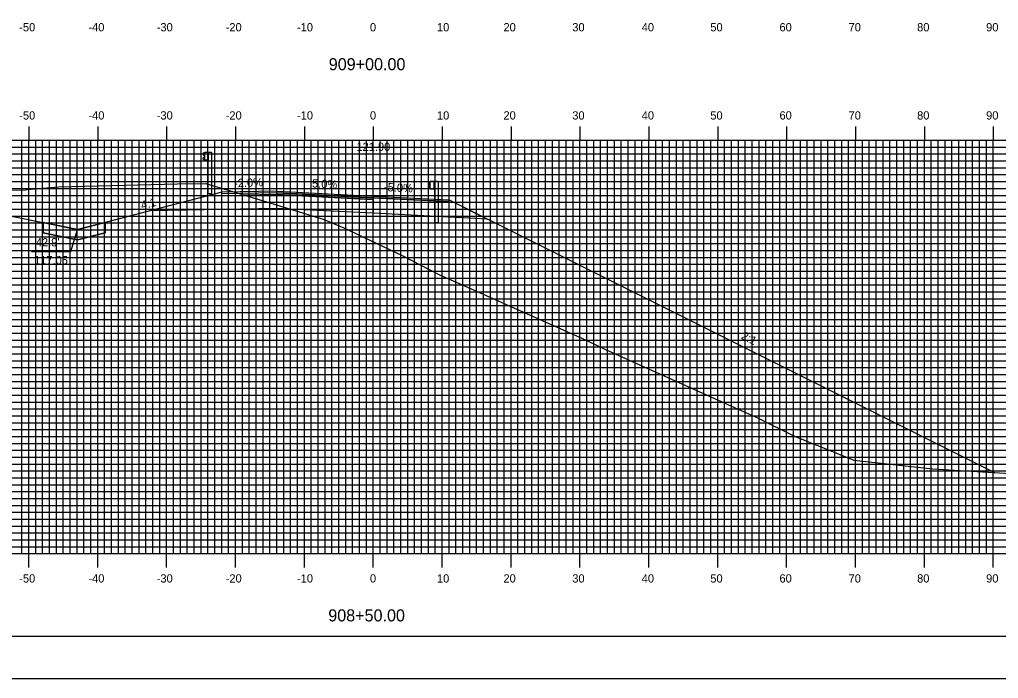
# Model space of a CAD drawing. Extents: x 858684 to 859027, y 364765 to 364985.
# Drawn here: x 858798.5 to 858940.6, y 364765.2 to 364860.8 of the extents above; entities that cross this region are included whole.
import ezdxf

# ---------------------------------------------------------------- set-up
doc = ezdxf.new("R2010")
doc.units = 0
for name, color, linetype in [('ANNOTATION', 7, 'Continuous'), ('BORDER', 7, 'Continuous'), ('D_Guardrail_Beam_Rt', 7, 'Continuous'), ('D_Roadway_Centerline', 7, 'Continuous'), ('D_Roadway_Centerline_Text', 7, 'Continuous'), ('D_Roadway_Edge_Shoulder', 7, 'Continuous'), ('D_Roadway_Edge_TW', 7, 'Continuous'), ('D_Roadway_FinishedGrade', 7, 'Continuous'), ('D_Roadway_Pavement', 7, 'Continuous'), ('D_Roadway_SlopeLines', 7, 'Continuous'), ('D_Roadway_SubGrade', 7, 'Continuous'), ('H_V ANNOTATION', 7, 'Continuous'), ('M_Guardrail', 7, 'Continuous'), ('M_Roadway_Centerline', 7, 'Continuous'), ('MAJOR', 7, 'Continuous'), ('MINOR', 7, 'Continuous'), ('PLOT BOUNDARY', 7, 'Continuous'), ('S_Roadway_Centerline', 7, 'Continuous')]:
    doc.layers.add(name, color=color, linetype=linetype)

msp = doc.modelspace()

# ---------------------------------------------------------------- linework, layer by layer
at = {"layer": 'ANNOTATION'}
msp.add_lwpolyline([(858800.26, 364827.16), (858805.95, 364827.16), (858806.92, 364830.35)], dxfattribs=at)
at = {"layer": 'BORDER'}
msp.add_lwpolyline([(858700.25, 364771.3), (859020.25, 364771.3), (859020.25, 364981.3), (858700.25, 364981.3)], close=True, dxfattribs=at)
at = {"layer": 'D_Guardrail_Beam_Rt'}
for p, q in [((858858.03, 364837.27), (858857.88, 364837.17)), ((858857.88, 364837.03), (858858.08, 364836.89)), ((858858.12, 364837.3), (858858.04, 364837.28)), ((858858.11, 364836.83), (858858.11, 364836.76)), ((858858.12, 364837.38), (858858.81, 364837.38)), ((858858.12, 364836.21), (858858.12, 364837.38)), ((858858.64, 364837.38), (858858.64, 364836.21)), ((858858.74, 364837.38), (858858.74, 364836.21)), ((858858.81, 364837.38), (858859.28, 364837.38)), ((858858.81, 364837.38), (858858.81, 364836.21)), ((858859.28, 364837.38), (858859.28, 364831.38)), ((858858.08, 364836.7), (858857.88, 364836.56)), ((858857.88, 364836.42), (858858.03, 364836.32)), ((858858.04, 364836.31), (858858.12, 364836.3)), ((858858.81, 364836.21), (858858.12, 364836.21)), ((858858.78, 364831.38), (858858.78, 364836.21)), ((858858.78, 364831.38), (858859.28, 364831.38))]:
    msp.add_line(p, q, dxfattribs=at)
for centre, major_axis, start_param, end_param in [((858857.94, 364837.1), (-0.0877, 0), 5.323254, 7.243116), ((858858.05, 364837.24), (-0.0417, 0), 4.907132, 5.323254), ((858858.03, 364836.83), (0.0789, 0), 0, 0.959931), ((858857.94, 364836.49), (-0.0877, 0), 5.323254, 7.243116), ((858858.05, 364836.35), (-0.0417, 0), 0.959931, 1.376053), ((858858.03, 364836.76), (0.0789, 0), 5.323254, 6.283185)]:
    msp.add_ellipse(centre, major_axis=major_axis, ratio=0.995501, start_param=start_param, end_param=end_param, dxfattribs=at)
at = {"layer": 'D_Roadway_Centerline'}
msp.add_lwpolyline([(858780.52, 364835.65), (858806.92, 364830.35)], dxfattribs=at)
at = {"layer": 'D_Roadway_Edge_Shoulder'}
for p, q in [((858835.85, 364835.91), (858827.85, 364835.75)), ((858827.85, 364835.5), (858827.85, 364835.75)), ((858835.85, 364835.66), (858827.85, 364835.5)), ((858830.85, 364835.46), (858830.85, 364835.56))]:
    msp.add_line(p, q, dxfattribs=at)
msp.add_lwpolyline([(858835.85, 364835.41), (858830.85, 364835.31), (858830.85, 364835.46)], dxfattribs=at)
msp.add_lwpolyline([(858849.85, 364835.2), (858857.85, 364834.8), (858857.85, 364834.8), (858860.85, 364834.64), (858860.85, 364834.39), (858849.85, 364834.95)], close=True, dxfattribs=at)
at = {"layer": 'D_Roadway_Edge_TW'}
msp.add_lwpolyline([(858835.85, 364835.91), (858849.85, 364835.2), (858849.85, 364834.95), (858835.85, 364835.66)], close=True, dxfattribs=at)
at = {"layer": 'D_Roadway_FinishedGrade'}
msp.add_line((858810.92, 364831.35), (858806.92, 364830.35), dxfattribs=at)
msp.add_lwpolyline([(858810.92, 364831.35), (858810.92, 364829.85), (858806.92, 364828.85), (858801.94, 364829.85), (858801.94, 364831.35), (858806.92, 364830.35)], close=True, dxfattribs=at)
msp.add_lwpolyline([(858806.92, 364830.35), (858801.94, 364831.35), (858801.94, 364829.85), (858806.92, 364828.85), (858810.92, 364829.85), (858810.92, 364831.35)], dxfattribs=at)
at = {"layer": 'D_Roadway_Pavement'}
msp.add_lwpolyline([(858835.85, 364835.66), (858849.85, 364834.95), (858849.85, 364834.7), (858835.85, 364835.41)], close=True, dxfattribs=at)
msp.add_lwpolyline([(858849.85, 364834.95), (858849.85, 364834.7)], dxfattribs=at)
msp.add_lwpolyline([(858849.85, 364834.95), (858849.85, 364834.7)], dxfattribs=at)
msp.add_lwpolyline([(858849.85, 364834.95), (858849.85, 364834.7)], dxfattribs=at)
at = {"layer": 'D_Roadway_SlopeLines'}
for p, q in [((858827.85, 364835.75), (858810.92, 364831.35)), ((858835.85, 364833.41), (858817.41, 364833.04))]:
    msp.add_line(p, q, dxfattribs=at)
msp.add_lwpolyline([(858860.85, 364834.64), (858940.02, 364795.06)], dxfattribs=at)
at = {"layer": 'D_Roadway_SubGrade'}
for points in [[(858835.85, 364835.41), (858849.85, 364834.7), (858849.85, 364832.7), (858835.85, 364833.41)], [(858849.85, 364834.7), (858849.85, 364834.95), (858860.85, 364834.39), (858860.85, 364834.64), (858866.41, 364831.86), (858849.85, 364832.7)]]:
    msp.add_lwpolyline(points, close=True, dxfattribs=at)
at = {"layer": 'M_Guardrail'}
for p, q in [((858825.28, 364841.45), (858825.14, 364841.35)), ((858825.14, 364841.21), (858825.33, 364841.07)), ((858825.38, 364841.47), (858825.3, 364841.46)), ((858825.38, 364841.55), (858825.87, 364841.55)), ((858825.38, 364840.38), (858825.38, 364841.55)), ((858825.87, 364841.55), (858826.36, 364841.55)), ((858825.87, 364841.55), (858825.87, 364840.38)), ((858826.36, 364841.55), (858826.36, 364835.55)), ((858825.33, 364840.85), (858825.14, 364840.72)), ((858825.14, 364840.57), (858825.28, 364840.47)), ((858825.3, 364840.47), (858825.38, 364840.45)), ((858825.37, 364841.01), (858825.37, 364840.92)), ((858825.87, 364840.38), (858825.38, 364840.38)), ((858825.87, 364835.55), (858825.87, 364840.38)), ((858825.87, 364835.55), (858826.36, 364835.55))]:
    msp.add_line(p, q, dxfattribs=at)
for centre, major_axis, start_param, end_param in [((858825.19, 364841.28), (-0.0877, 0), 5.323254, 7.243116), ((858825.3, 364841.42), (-0.0417, 0), 4.886922, 5.323254), ((858825.19, 364840.65), (-0.0877, 0), 5.323254, 7.243116), ((858825.3, 364840.51), (-0.0417, 0), 0.959931, 1.396263), ((858825.29, 364841.01), (0.0789, 0), 0, 0.959931), ((858825.29, 364840.92), (0.0789, 0), 5.323254, 6.283185)]:
    msp.add_ellipse(centre, major_axis=major_axis, ratio=0.995501, start_param=start_param, end_param=end_param, dxfattribs=at)
at = {"layer": 'MAJOR'}
for p, q in [((858799.85, 364845.31), (858799.85, 364843.3)), ((858809.85, 364845.31), (858809.85, 364843.3)), ((858819.85, 364845.31), (858819.85, 364843.3)), ((858829.85, 364845.31), (858829.85, 364843.3)), ((858839.85, 364845.31), (858839.85, 364843.3)), ((858849.85, 364845.31), (858849.85, 364843.3)), ((858859.85, 364845.31), (858859.85, 364843.3)), ((858869.85, 364845.31), (858869.85, 364843.3)), ((858879.85, 364845.31), (858879.85, 364843.3)), ((858889.85, 364845.31), (858889.85, 364843.3)), ((858899.85, 364845.31), (858899.85, 364843.3)), ((858909.85, 364845.31), (858909.85, 364843.3)), ((858919.85, 364845.31), (858919.85, 364843.3)), ((858929.85, 364845.31), (858929.85, 364843.3)), ((858939.85, 364845.31), (858939.85, 364843.3)), ((858709.85, 364843.3), (858989.85, 364843.3)), ((858709.85, 364843.3), (858989.85, 364843.3)), ((858799.85, 364783.3), (858799.85, 364843.3)), ((858809.85, 364783.3), (858809.85, 364843.3)), ((858819.85, 364783.3), (858819.85, 364843.3)), ((858829.85, 364783.3), (858829.85, 364843.3)), ((858839.85, 364783.3), (858839.85, 364843.3)), ((858849.85, 364783.3), (858849.85, 364843.3)), ((858859.85, 364783.3), (858859.85, 364843.3)), ((858869.85, 364783.3), (858869.85, 364843.3)), ((858879.85, 364783.3), (858879.85, 364843.3)), ((858889.85, 364783.3), (858889.85, 364843.3)), ((858899.85, 364783.3), (858899.85, 364843.3)), ((858909.85, 364783.3), (858909.85, 364843.3)), ((858919.85, 364783.3), (858919.85, 364843.3)), ((858929.85, 364783.3), (858929.85, 364843.3)), ((858939.85, 364783.3), (858939.85, 364843.3)), ((858709.85, 364838.3), (858989.85, 364838.3)), ((858709.85, 364833.3), (858989.85, 364833.3)), ((858709.85, 364828.3), (858989.85, 364828.3)), ((858709.85, 364823.3), (858989.85, 364823.3)), ((858709.85, 364818.3), (858989.85, 364818.3)), ((858709.85, 364813.3), (858989.85, 364813.3)), ((858709.85, 364808.3), (858989.85, 364808.3)), ((858709.85, 364803.3), (858989.85, 364803.3)), ((858709.85, 364798.3), (858989.85, 364798.3)), ((858709.85, 364793.3), (858989.85, 364793.3)), ((858709.85, 364788.3), (858989.85, 364788.3)), ((858709.85, 364783.3), (858989.85, 364783.3)), ((858709.85, 364783.3), (858989.85, 364783.3)), ((858799.85, 364781.3), (858799.85, 364783.3)), ((858809.85, 364781.3), (858809.85, 364783.3)), ((858819.85, 364781.3), (858819.85, 364783.3)), ((858829.85, 364781.3), (858829.85, 364783.3)), ((858839.85, 364781.3), (858839.85, 364783.3)), ((858849.85, 364781.3), (858849.85, 364783.3)), ((858859.85, 364781.3), (858859.85, 364783.3)), ((858869.85, 364781.3), (858869.85, 364783.3)), ((858879.85, 364781.3), (858879.85, 364783.3)), ((858889.85, 364781.3), (858889.85, 364783.3)), ((858899.85, 364781.3), (858899.85, 364783.3)), ((858909.85, 364781.3), (858909.85, 364783.3)), ((858919.85, 364781.3), (858919.85, 364783.3)), ((858929.85, 364781.3), (858929.85, 364783.3)), ((858939.85, 364781.3), (858939.85, 364783.3))]:
    msp.add_line(p, q, dxfattribs=at)
at = {"layer": 'MINOR'}
for p, q in [((858798.85, 364783.3), (858798.85, 364843.3)), ((858800.85, 364783.3), (858800.85, 364843.3)), ((858801.85, 364783.3), (858801.85, 364843.3)), ((858802.85, 364783.3), (858802.85, 364843.3)), ((858803.85, 364783.3), (858803.85, 364843.3)), ((858804.85, 364783.3), (858804.85, 364843.3)), ((858805.85, 364783.3), (858805.85, 364843.3)), ((858806.85, 364783.3), (858806.85, 364843.3)), ((858807.85, 364783.3), (858807.85, 364843.3)), ((858808.85, 364783.3), (858808.85, 364843.3)), ((858810.85, 364783.3), (858810.85, 364843.3)), ((858811.85, 364783.3), (858811.85, 364843.3)), ((858812.85, 364783.3), (858812.85, 364843.3)), ((858813.85, 364783.3), (858813.85, 364843.3)), ((858814.85, 364783.3), (858814.85, 364843.3)), ((858815.85, 364783.3), (858815.85, 364843.3)), ((858816.85, 364783.3), (858816.85, 364843.3)), ((858817.85, 364783.3), (858817.85, 364843.3)), ((858818.85, 364783.3), (858818.85, 364843.3)), ((858820.85, 364783.3), (858820.85, 364843.3)), ((858821.85, 364783.3), (858821.85, 364843.3)), ((858822.85, 364783.3), (858822.85, 364843.3)), ((858823.85, 364783.3), (858823.85, 364843.3)), ((858824.85, 364783.3), (858824.85, 364843.3)), ((858825.85, 364783.3), (858825.85, 364843.3)), ((858826.85, 364783.3), (858826.85, 364843.3)), ((858827.85, 364783.3), (858827.85, 364843.3)), ((858828.85, 364783.3), (858828.85, 364843.3)), ((858830.85, 364783.3), (858830.85, 364843.3)), ((858831.85, 364783.3), (858831.85, 364843.3)), ((858832.85, 364783.3), (858832.85, 364843.3)), ((858833.85, 364783.3), (858833.85, 364843.3)), ((858834.85, 364783.3), (858834.85, 364843.3)), ((858835.85, 364783.3), (858835.85, 364843.3)), ((858836.85, 364783.3), (858836.85, 364843.3)), ((858837.85, 364783.3), (858837.85, 364843.3)), ((858838.85, 364783.3), (858838.85, 364843.3)), ((858840.85, 364783.3), (858840.85, 364843.3)), ((858841.85, 364783.3), (858841.85, 364843.3)), ((858842.85, 364783.3), (858842.85, 364843.3)), ((858843.85, 364783.3), (858843.85, 364843.3)), ((858844.85, 364783.3), (858844.85, 364843.3)), ((858845.85, 364783.3), (858845.85, 364843.3)), ((858846.85, 364783.3), (858846.85, 364843.3)), ((858847.85, 364783.3), (858847.85, 364843.3)), ((858848.85, 364783.3), (858848.85, 364843.3)), ((858850.85, 364783.3), (858850.85, 364843.3)), ((858851.85, 364783.3), (858851.85, 364843.3)), ((858852.85, 364783.3), (858852.85, 364843.3)), ((858853.85, 364783.3), (858853.85, 364843.3)), ((858854.85, 364783.3), (858854.85, 364843.3)), ((858855.85, 364783.3), (858855.85, 364843.3)), ((858856.85, 364783.3), (858856.85, 364843.3)), ((858857.85, 364783.3), (858857.85, 364843.3)), ((858858.85, 364783.3), (858858.85, 364843.3)), ((858860.85, 364783.3), (858860.85, 364843.3)), ((858861.85, 364783.3), (858861.85, 364843.3)), ((858862.85, 364783.3), (858862.85, 364843.3)), ((858863.85, 364783.3), (858863.85, 364843.3)), ((858864.85, 364783.3), (858864.85, 364843.3)), ((858865.85, 364783.3), (858865.85, 364843.3)), ((858866.85, 364783.3), (858866.85, 364843.3)), ((858867.85, 364783.3), (858867.85, 364843.3)), ((858868.85, 364783.3), (858868.85, 364843.3)), ((858870.85, 364783.3), (858870.85, 364843.3)), ((858871.85, 364783.3), (858871.85, 364843.3)), ((858872.85, 364783.3), (858872.85, 364843.3)), ((858873.85, 364783.3), (858873.85, 364843.3)), ((858874.85, 364783.3), (858874.85, 364843.3)), ((858875.85, 364783.3), (858875.85, 364843.3)), ((858876.85, 364783.3), (858876.85, 364843.3)), ((858877.85, 364783.3), (858877.85, 364843.3)), ((858878.85, 364783.3), (858878.85, 364843.3)), ((858880.85, 364783.3), (858880.85, 364843.3)), ((858881.85, 364783.3), (858881.85, 364843.3)), ((858882.85, 364783.3), (858882.85, 364843.3)), ((858883.85, 364783.3), (858883.85, 364843.3)), ((858884.85, 364783.3), (858884.85, 364843.3)), ((858885.85, 364783.3), (858885.85, 364843.3)), ((858886.85, 364783.3), (858886.85, 364843.3)), ((858887.85, 364783.3), (858887.85, 364843.3)), ((858888.85, 364783.3), (858888.85, 364843.3)), ((858890.85, 364783.3), (858890.85, 364843.3)), ((858891.85, 364783.3), (858891.85, 364843.3)), ((858892.85, 364783.3), (858892.85, 364843.3)), ((858893.85, 364783.3), (858893.85, 364843.3)), ((858894.85, 364783.3), (858894.85, 364843.3)), ((858895.85, 364783.3), (858895.85, 364843.3)), ((858896.85, 364783.3), (858896.85, 364843.3)), ((858897.85, 364783.3), (858897.85, 364843.3)), ((858898.85, 364783.3), (858898.85, 364843.3)), ((858900.85, 364783.3), (858900.85, 364843.3)), ((858901.85, 364783.3), (858901.85, 364843.3)), ((858902.85, 364783.3), (858902.85, 364843.3)), ((858903.85, 364783.3), (858903.85, 364843.3)), ((858904.85, 364783.3), (858904.85, 364843.3)), ((858905.85, 364783.3), (858905.85, 364843.3)), ((858906.85, 364783.3), (858906.85, 364843.3)), ((858907.85, 364783.3), (858907.85, 364843.3)), ((858908.85, 364783.3), (858908.85, 364843.3)), ((858910.85, 364783.3), (858910.85, 364843.3)), ((858911.85, 364783.3), (858911.85, 364843.3)), ((858912.85, 364783.3), (858912.85, 364843.3)), ((858913.85, 364783.3), (858913.85, 364843.3)), ((858914.85, 364783.3), (858914.85, 364843.3)), ((858915.85, 364783.3), (858915.85, 364843.3)), ((858916.85, 364783.3), (858916.85, 364843.3)), ((858917.85, 364783.3), (858917.85, 364843.3)), ((858918.85, 364783.3), (858918.85, 364843.3)), ((858920.85, 364783.3), (858920.85, 364843.3)), ((858921.85, 364783.3), (858921.85, 364843.3)), ((858922.85, 364783.3), (858922.85, 364843.3)), ((858923.85, 364783.3), (858923.85, 364843.3)), ((858924.85, 364783.3), (858924.85, 364843.3)), ((858925.85, 364783.3), (858925.85, 364843.3)), ((858926.85, 364783.3), (858926.85, 364843.3)), ((858927.85, 364783.3), (858927.85, 364843.3)), ((858928.85, 364783.3), (858928.85, 364843.3)), ((858930.85, 364783.3), (858930.85, 364843.3)), ((858931.85, 364783.3), (858931.85, 364843.3)), ((858932.85, 364783.3), (858932.85, 364843.3)), ((858933.85, 364783.3), (858933.85, 364843.3)), ((858934.85, 364783.3), (858934.85, 364843.3)), ((858935.85, 364783.3), (858935.85, 364843.3)), ((858936.85, 364783.3), (858936.85, 364843.3)), ((858937.85, 364783.3), (858937.85, 364843.3)), ((858938.85, 364783.3), (858938.85, 364843.3)), ((858709.85, 364842.3), (858989.85, 364842.3)), ((858709.85, 364841.3), (858989.85, 364841.3)), ((858709.85, 364840.3), (858989.85, 364840.3)), ((858709.85, 364839.3), (858989.85, 364839.3)), ((858709.85, 364837.3), (858989.85, 364837.3)), ((858709.85, 364836.3), (858989.85, 364836.3)), ((858709.85, 364835.3), (858989.85, 364835.3)), ((858709.85, 364834.3), (858989.85, 364834.3)), ((858709.85, 364832.3), (858989.85, 364832.3)), ((858709.85, 364831.3), (858989.85, 364831.3)), ((858709.85, 364830.3), (858989.85, 364830.3)), ((858709.85, 364829.3), (858989.85, 364829.3)), ((858709.85, 364827.3), (858989.85, 364827.3)), ((858709.85, 364826.3), (858989.85, 364826.3)), ((858709.85, 364825.3), (858989.85, 364825.3)), ((858709.85, 364824.3), (858989.85, 364824.3)), ((858709.85, 364822.3), (858989.85, 364822.3)), ((858709.85, 364821.3), (858989.85, 364821.3)), ((858709.85, 364820.3), (858989.85, 364820.3)), ((858709.85, 364819.3), (858989.85, 364819.3)), ((858709.85, 364817.3), (858989.85, 364817.3)), ((858709.85, 364816.3), (858989.85, 364816.3)), ((858709.85, 364815.3), (858989.85, 364815.3)), ((858709.85, 364814.3), (858989.85, 364814.3)), ((858709.85, 364812.3), (858989.85, 364812.3)), ((858709.85, 364811.3), (858989.85, 364811.3)), ((858709.85, 364810.3), (858989.85, 364810.3)), ((858709.85, 364809.3), (858989.85, 364809.3)), ((858709.85, 364807.3), (858989.85, 364807.3)), ((858709.85, 364806.3), (858989.85, 364806.3)), ((858709.85, 364805.3), (858989.85, 364805.3)), ((858709.85, 364804.3), (858989.85, 364804.3)), ((858709.85, 364802.3), (858989.85, 364802.3)), ((858709.85, 364801.3), (858989.85, 364801.3)), ((858709.85, 364800.3), (858989.85, 364800.3)), ((858709.85, 364799.3), (858989.85, 364799.3)), ((858709.85, 364797.3), (858989.85, 364797.3)), ((858709.85, 364796.3), (858989.85, 364796.3)), ((858709.85, 364795.3), (858989.85, 364795.3)), ((858709.85, 364794.3), (858989.85, 364794.3)), ((858709.85, 364792.3), (858989.85, 364792.3)), ((858709.85, 364791.3), (858989.85, 364791.3)), ((858709.85, 364790.3), (858989.85, 364790.3)), ((858709.85, 364789.3), (858989.85, 364789.3)), ((858709.85, 364787.3), (858989.85, 364787.3)), ((858709.85, 364786.3), (858989.85, 364786.3)), ((858709.85, 364785.3), (858989.85, 364785.3)), ((858709.85, 364784.3), (858989.85, 364784.3))]:
    msp.add_line(p, q, dxfattribs=at)
at = {"layer": 'PLOT BOUNDARY'}
msp.add_lwpolyline([(858684.06, 364765.18), (859024.06, 364765.18), (859024.06, 364985.18), (858684.06, 364985.18)], close=True, dxfattribs=at)
at = {"layer": 'S_Roadway_Centerline'}
msp.add_lwpolyline([(858778.73, 364835.61), (858799.39, 364836.12), (858799.55, 364836.13), (858799.56, 364836.13), (858799.6, 364836.13), (858804.16, 364836.54), (858821.41, 364836.95), (858825.54, 364837.03), (858832.61, 364834.87), (858842.57, 364831.85), (858845.59, 364830.58), (858854.04, 364826.59), (858859.46, 364823.77), (858863.08, 364822.17), (858880.2, 364814.51), (858882.04, 364813.64), (858883.58, 364812.94), (858905.61, 364803), (858911, 364800.36), (858919.61, 364796.85), (858931.03, 364795.61), (858948.81, 364794.52)], dxfattribs=at)

# ---------------------------------------------------------------- texts
at = {"layer": 'ANNOTATION'}
for s, rotation, p in [('-2.0%', 2.2907, (858829.67, 364836.46)), ('5.0%', 357.1132, (858840.94, 364836.45)), ('-5.0%', 357.109, (858851.38, 364835.92)), ('4:1', 14.0362, (858816.27, 364833.24)), ('2:1', 333.4343, (858903.15, 364814.53))]:
    msp.add_text(s, height=1.2, rotation=rotation, dxfattribs=at).set_placement(p)
for s, p in [("42.9' ", (858800.87, 364827.89)), ('117.05', (858800.62, 364825.29))]:
    msp.add_text(s, height=1.2, dxfattribs=at).set_placement(p)
at = {"layer": 'D_Roadway_Centerline_Text'}
msp.add_text('121.90', height=1.2, dxfattribs=at).set_placement((858847.41, 364841.75))
at = {"layer": 'H_V ANNOTATION'}
for s, height, p in [('-50', 1.2, (858798.46, 364859.1)), ('-40', 1.2, (858808.5, 364859.1)), ('-30', 1.2, (858818.42, 364859.1)), ('-20', 1.2, (858828.43, 364859.1)), ('-10', 1.2, (858838.78, 364859.1)), ('0', 1.2, (858849.37, 364859.1)), ('10', 1.2, (858859.1, 364859.1)), ('20', 1.2, (858868.75, 364859.1)), ('30', 1.2, (858878.74, 364859.1)), ('40', 1.2, (858888.82, 364859.1)), ('50', 1.2, (858898.78, 364859.1)), ('60', 1.2, (858908.82, 364859.1)), ('70', 1.2, (858918.85, 364859.1)), ('80', 1.2, (858928.8, 364859.1)), ('90', 1.2, (858938.82, 364859.1)), ('909+00.00', 1.75, (858843.39, 364853.46)), ('-50', 1.2, (858798.46, 364846.3)), ('-40', 1.2, (858808.5, 364846.3)), ('-30', 1.2, (858818.42, 364846.3)), ('-20', 1.2, (858828.43, 364846.3)), ('-10', 1.2, (858838.78, 364846.3)), ('0', 1.2, (858849.37, 364846.3)), ('10', 1.2, (858859.1, 364846.3)), ('20', 1.2, (858868.75, 364846.3)), ('30', 1.2, (858878.74, 364846.3)), ('40', 1.2, (858888.82, 364846.3)), ('50', 1.2, (858898.78, 364846.3)), ('60', 1.2, (858908.82, 364846.3)), ('70', 1.2, (858918.85, 364846.3)), ('80', 1.2, (858928.8, 364846.3)), ('90', 1.2, (858938.82, 364846.3)), ('-50', 1.2, (858798.46, 364779.1)), ('-40', 1.2, (858808.5, 364779.1)), ('-30', 1.2, (858818.42, 364779.1)), ('-20', 1.2, (858828.43, 364779.1)), ('-10', 1.2, (858838.78, 364779.1)), ('0', 1.2, (858849.37, 364779.1)), ('10', 1.2, (858859.1, 364779.1)), ('20', 1.2, (858868.75, 364779.1)), ('30', 1.2, (858878.74, 364779.1)), ('40', 1.2, (858888.82, 364779.1)), ('50', 1.2, (858898.78, 364779.1)), ('60', 1.2, (858908.82, 364779.1)), ('70', 1.2, (858918.85, 364779.1)), ('80', 1.2, (858928.8, 364779.1)), ('90', 1.2, (858938.82, 364779.1)), ('908+50.00', 1.75, (858843.32, 364773.46))]:
    msp.add_text(s, height=height, dxfattribs=at).set_placement(p)
at = {"layer": 'M_Roadway_Centerline'}
for s, p in [('C', (858804.16, 364836.54)), ('L', (858804.16, 364836.53))]:
    msp.add_text(s, height=0.0146, dxfattribs=at).set_placement(p)

doc.saveas('drawing.dxf')
